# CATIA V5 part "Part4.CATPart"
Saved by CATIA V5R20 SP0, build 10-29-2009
Part number: Part4
Bounding box of the stored display mesh (mm): x 0 to 13, y -5 to 5, z -4.33 to 4.33
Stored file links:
  C:\Users\YS\Desktop\독수리\Part4.CATPart
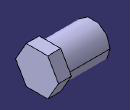
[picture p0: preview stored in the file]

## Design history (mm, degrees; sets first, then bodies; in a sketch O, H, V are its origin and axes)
Body1 (main body)
  Sketch1 on yz-plane, origin (0, 0, 0), H (0, 1, 0), V (0, 0, 1)
    circle A1 centre (0, 0) radius 4
    radius A1 = 4
  Pad1: profile Sketch1, direction (1, 0, 0), length 10
  Sketch2 on end face of Pad1, origin (10, 0, 0), H (0, 1, 0), V (0, 0, 1)
    point P1 (0, 0)
    point P2 (5, 0)
    point P3 (2.5, 4.3301)
    point P4 (-2.5, 4.3301)
    point P5 (-5, 0)
    point P6 (-2.5, -4.3301)
    point P7 (2.5, -4.3301)
    point P8 (3.75, 2.1651)
    line L1 (5, 0) -> (2.5, 4.3301)
    line L2 (2.5, 4.3301) -> (-2.5, 4.3301)
    line L3 (-2.5, 4.3301) -> (-5, 0)
    line L4 (-5, 0) -> (-2.5, -4.3301)
    line L5 (-2.5, -4.3301) -> (2.5, -4.3301)
    line L6 (2.5, -4.3301) -> (5, 0)
    construction line L7 (0, 0) -> (3.75, 2.1651)
    construction circle A1 centre (0, 0) radius 5
    construction arc A2 centre (-2.5, -4.3301) radius 5 from (-5, 0) to (2.5, -4.3301) cw
    construction arc A3 centre (2.5, 4.3301) radius 5 from (-2.5, 4.3301) to (5, 0) ccw
    length L2 = 5
    coincidence: A1 P2, A1 P3, A1 P4, A1 P5, A1 P6, A1 P7, A2 P1, A3 P1, P1 O
    midpoint: P8 L1
    parallelism: L1 L4
    horizontal: L2 H
  Pad2: profile Sketch2, direction (1, 0, 0), length 3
